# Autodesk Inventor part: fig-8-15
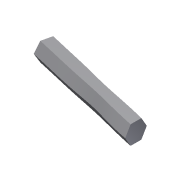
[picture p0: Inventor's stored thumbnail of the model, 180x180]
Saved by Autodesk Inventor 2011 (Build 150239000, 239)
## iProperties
Created: 2004-05
Part Number: fig-8-15
Document SubType Name: Modeling
Designer: CADCIM Technologies
Manufacturer: Standard
Standards Organization: Custom
Density: 1 g/cm^3
Author: CADCIM Technologies
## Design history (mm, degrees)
workplane "Work Plane2"
sketch "Sketch7"
  geometry: L1 (-42.583, 6.068)-(-42.583, 0.37) reference; 5 further points
  constraints: 1 point on line, 5 other
sketch "Sketch8"
  geometry: L1 (-42.583, 3.219)-(-107.269, 18.236); L2 (-42.583, 6.068)-(-42.583, 0.37) reference
  constraints: 2 end point, 1 midpoint
sweep "Sweep7" sketch "Sketch7", "Sketch8" dims "d6" = 0
body "Solid1"
sketch "Sketch2"
  geometry: L1 (-5.697, 0)-(-2.849, 4.934); L2 (-2.849, 4.934)-(2.849, 4.934); L3 (2.849, 4.934)-(5.697, 0); L4 (5.697, 0)-(2.849, -4.934); L5 (2.849, -4.934)-(-2.849, -4.934); L6 (-2.849, -4.934)-(-5.697, 0); 2 further points
  constraints: 12 end point, 1 coincident, 12 other
